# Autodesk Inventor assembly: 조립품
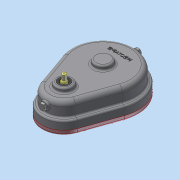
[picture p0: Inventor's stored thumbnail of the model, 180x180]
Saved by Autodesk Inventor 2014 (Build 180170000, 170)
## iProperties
Created: 2024-05
Part Number: 조립품
Document SubType Name: Assembly
Designer: dg
Author: dg
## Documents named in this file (13)
- C:\Users\dg\Desktop\740504V1007\조립품.iam
- C:\Users\dg\Desktop\740504V1007\본체.ipt
- C:\Users\dg\Desktop\740504V1007\가져온 구성요소\오일리스 부시\오일리스 부시.ipt
- C:\Users\dg\Desktop\740504V1007\가져온 구성요소\하단 축\하단 축.ipt
- C:\Users\dg\Desktop\740504V1007\가져온 구성요소\오일 실 10 20 4\오일 실 10 20 4.ipt
- C:\Users\dg\Desktop\740504V1007\가져온 구성요소\평행키 5x5x12\평행키 5x5x12.ipt
- C:\Users\dg\Desktop\740504V1007\가져온 구성요소\상단 축\상단 축.ipt
- C:\Users\dg\Desktop\740504V1007\가져온 구성요소\스퍼기어A\스퍼기어A.ipt
- C:\Users\dg\Desktop\740504V1007\가져온 구성요소\스퍼기어B\스퍼기어B.ipt
- C:\Users\dg\Desktop\740504V1007\가져온 구성요소\육각 머리 볼트  M6x0.75x6\육각 머리 볼트  M6x0.75x6.ipt
- C:\Users\dg\Desktop\740504V1007\가져온 구성요소\커버\커버.ipt
- C:\Users\dg\Desktop\740504V1007\가져온 구성요소\육각 소켓 머리 볼트 M4x10\육각 소켓 머리 볼트 M4x10.ipt
- C:\Users\dg\Desktop\740504V1007\가져온 구성요소\육각 소켓 머리 볼트 M4x10\육각 소켓 머리 볼트 M4x10_MIR.ipt
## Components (1 placed, 1 different names)
1. 하단 축:1
